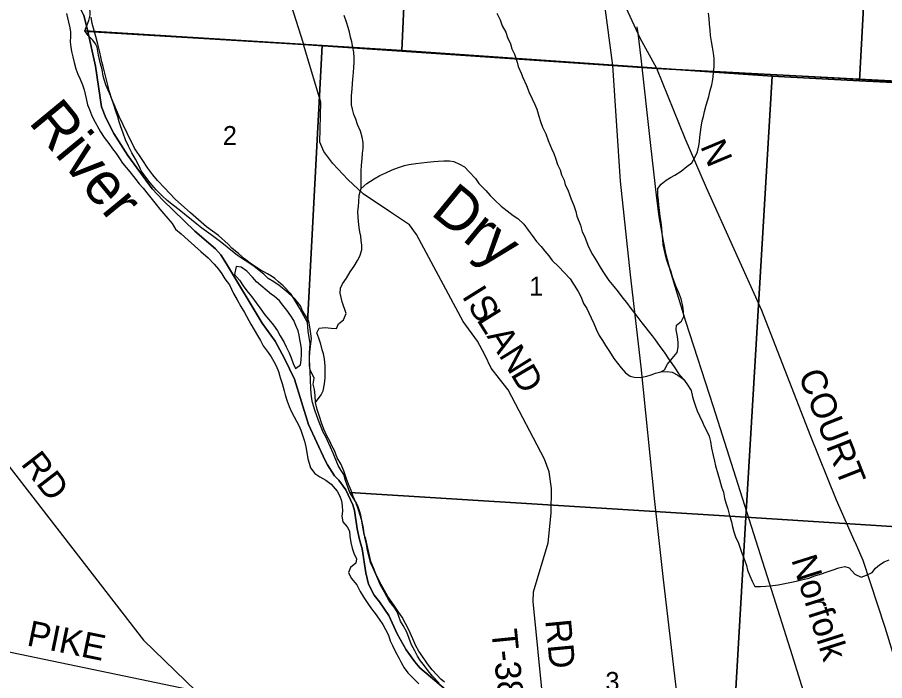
# Model space of a CAD drawing. Extents: x 1643459 to 2064572, y 425441 to 780708.
# Drawn here: x 1832459 to 1842600, y 595739 to 603499 of the extents above; entities that cross this region are included whole.
import ezdxf

# ---------------------------------------------------------------- set-up
doc = ezdxf.new("R2010")
doc.units = 0
for name, color, linetype in [('GM_X_Adjacent_County', 7, 'Continuous'), ('GM_X_City_Street', 7, 'Continuous'), ('GM_X_Interchange_Ramps', 7, 'Continuous'), ('GM_X_Major_River', 7, 'Continuous'), ('GM_X_Major_River_Text', 7, 'Continuous'), ('GM_X_Minor_Lake', 7, 'Continuous'), ('GM_X_Section_Text', 7, 'Continuous'), ('GM_X_State_Route', 7, 'Continuous'), ('GM_X_State_Shield', 7, 'Continuous'), ('GM_X_Township_Road', 7, 'Continuous'), ('GM_X_Township_Road_Text', 7, 'Continuous'), ('GM_X_Unincorporated_Text', 7, 'Continuous'), ('GM_X_US_Route', 7, 'Continuous'), ('RD_X_Wall', 7, 'Continuous')]:
    doc.layers.add(name, color=color, linetype=linetype)

msp = doc.modelspace()

# ---------------------------------------------------------------- linework, layer by layer
at = {"layer": 'GM_X_City_Street'}
for points in [[(1851890, 602317), (1849051, 602434), (1847771, 602487), (1839937, 602900), (1839420, 602936), (1835806, 603183), (1833283, 603334), (1833235, 603525), (1833196, 603598), (1833111, 603919), (1832921, 604454), (1832836, 604727), (1832753, 604952), (1832707, 605041), (1832613, 605226), (1832458, 605407)], [(1833235, 603525), (1833283, 603334), (1833372, 602929), (1833444, 602453), (1833495, 602324), (1833589, 602141), (1833750, 601881), (1834035, 601491), (1834159, 601360), (1834533, 600999), (1834777, 600791), (1834838, 600719), (1834906, 600614), (1835322, 599920), (1835474, 599711), (1835581, 599509), (1835699, 599266), (1835863, 598734), (1836060, 598313), (1836084, 598263), (1836167, 598134), (1836219, 598084), (1836299, 597973), (1836380, 597796), (1836402, 597730), (1836433, 597517), (1836459, 597390), (1836490, 597282), (1836533, 596999), (1836565, 596868), (1836632, 596738), (1836694, 596663), (1836802, 596500), (1836899, 596289), (1837007, 596098), (1837105, 595961), (1837166, 595890), (1837466, 595634)], [(1837466, 595634), (1837166, 595890), (1837105, 595961), (1837007, 596098), (1836899, 596289), (1836802, 596500), (1836694, 596663), (1836632, 596738), (1836565, 596868), (1836533, 596999), (1836490, 597282), (1836459, 597390), (1836433, 597517), (1836402, 597730), (1836380, 597796), (1836299, 597973), (1836219, 598084), (1836167, 598134), (1836084, 598263), (1836060, 598313), (1835863, 598734), (1835699, 599266), (1835581, 599509), (1835474, 599711), (1835322, 599920), (1834906, 600614), (1834838, 600719), (1834777, 600791), (1834533, 600999), (1834159, 601360), (1834035, 601491), (1833750, 601881), (1833589, 602141), (1833495, 602324), (1833444, 602453), (1833372, 602929), (1833283, 603334), (1835806, 603183), (1839420, 602936), (1839937, 602900), (1847771, 602487)]]:
    msp.add_lwpolyline(points, dxfattribs=at)
at = {"layer": 'GM_X_Major_River_Text'}
for points in [[(1835803, 603192), (1835580, 603905), (1835098, 605134), (1834779, 605882), (1834163, 607311), (1836120, 607161), (1836492, 607280), (1836751, 607373), (1837278, 607428), (1837829, 607405)], [(1838603, 595525), (1838490, 596664), (1838495, 596777), (1838665, 597353), (1838702, 597700), (1838703, 597987), (1838679, 598184), (1838624, 598332), (1838198, 599141), (1838095, 599269), (1837999, 599394), (1837926, 599550), (1837840, 599712), (1837673, 599940), (1837127, 600960), (1837043, 601070), (1836824, 601218), (1836501, 601436), (1836322, 601602), (1836147, 601788), (1836041, 601931), (1835994, 602039), (1836008, 602507), (1835806, 603183), (1835803, 603192)], [(1841017, 602840), (1839937, 602900)], [(1845663, 602580), (1841017, 602840)]]:
    msp.add_lwpolyline(points, dxfattribs=at)
at = {"layer": 'GM_X_Minor_Lake'}
for points in [[(1827033, 605132), (1827729, 604232), (1833934, 596214), (1834549, 595618)], [(1839937, 602900), (1839740, 603257), (1839269, 604281), (1839118, 604504), (1839118, 604505)], [(1842256, 597357), (1842035, 597852), (1841727, 598614), (1841163, 600071), (1840518, 601504), (1840268, 602081), (1839937, 602900)], [(1834549, 595618), (1832020, 596144), (1828915, 595974), (1828795, 595972), (1828691, 596005), (1827711, 596647), (1827066, 597064), (1826478, 597464), (1826051, 597755), (1825576, 598057), (1825113, 598342), (1824724, 598588)], [(1843109, 594908), (1842842, 595587), (1842604, 596361), (1842350, 597145), (1842259, 597350), (1842256, 597357)]]:
    msp.add_lwpolyline(points, dxfattribs=at)
at = {"layer": 'GM_X_State_Route'}
for points in [[(1831814, 608761), (1837195, 608395), (1836955, 603110), (1836023, 603169), (1833250, 603342), (1833295, 603462), (1833309, 603524), (1833311, 603566), (1833194, 604051), (1833141, 604253), (1833003, 604686), (1832944, 604860), (1832888, 605022), (1832829, 605138), (1832759, 605243), (1832664, 605343), (1832548, 605466), (1832377, 605625)], [(1837452, 595722), (1837412, 595756), (1837362, 595806), (1837308, 595867), (1837255, 595937), (1837171, 596057), (1837153, 596083), (1837120, 596145), (1837084, 596230), (1837036, 596334), (1836957, 596484), (1836921, 596536), (1836864, 596617), (1836792, 596725), (1836713, 596865), (1836652, 596988), (1836622, 597058), (1836594, 597132), (1836532, 597396), (1836516, 597450), (1836504, 597516), (1836475, 597675), (1836463, 597715), (1836441, 597783), (1836412, 597837), (1836348, 597941), (1840975, 597651), (1840668, 592357)]]:
    msp.add_lwpolyline(points, dxfattribs=at)
for points in [[(1842595, 608085), (1842304, 602757), (1841286, 602812), (1836955, 603110), (1837195, 608395)], [(1842595, 608085), (1842604, 608253), (1846583, 608042), (1846349, 602557), (1842304, 602757)], [(1836023, 603169), (1835850, 599930), (1835808, 600006), (1835763, 600094), (1835715, 600170), (1835661, 600259), (1835566, 600359), (1835512, 600403), (1835468, 600442), (1835430, 600470), (1835383, 600498), (1835299, 600546), (1835183, 600623), (1835115, 600675), (1835048, 600732), (1834966, 600800), (1834924, 600844), (1834813, 600947), (1834671, 601049), (1834482, 601212), (1834306, 601373), (1834179, 601506), (1834098, 601592), (1834042, 601656), (1833983, 601735), (1833919, 601835), (1833828, 601970), (1833742, 602142), (1833651, 602338), (1833556, 602563), (1833547, 602585), (1833495, 602709), (1833464, 602809), (1833450, 602887), (1833432, 602955), (1833409, 603058), (1833391, 603150), (1833372, 603190), (1833342, 603230), (1833286, 603286), (1833250, 603342)], [(1836955, 603110), (1841286, 602812), (1840975, 597651), (1836348, 597941), (1836297, 598080), (1836277, 598150), (1836259, 598174), (1836244, 598196), (1836212, 598258), (1836152, 598400), (1836069, 598583), (1836034, 598645), (1835980, 598781), (1835937, 598905), (1835911, 598993), (1835898, 599061), (1835890, 599149), (1835885, 599268), (1835874, 599502), (1835874, 599576), (1835881, 599682), (1835873, 599752), (1835861, 599826), (1835850, 599930), (1836023, 603169)], [(1841286, 602812), (1842304, 602757), (1846349, 602557), (1846591, 602546), (1846274, 597313), (1840975, 597651)], [(1840975, 597651), (1846274, 597313), (1845968, 591981), (1840668, 592357)]]:
    msp.add_lwpolyline(points, close=True, dxfattribs=at)
at = {"layer": 'GM_X_Township_Road'}
msp.add_lwpolyline([(1841773, 595226), (1841521, 596029), (1841253, 596878), (1840600, 598944), (1840275, 599940), (1840094, 600530), (1840047, 600719), (1840014, 600880), (1839963, 601170), (1839936, 601385), (1839866, 602000), (1839751, 603020), (1839717, 603313), (1839706, 603388)], dxfattribs=at)
at = {"layer": 'GM_X_Unincorporated_Text'}
for points in [[(1833035, 603545), (1833045, 603493), (1833058, 603441), (1833074, 603377), (1833080, 603326), (1833082, 603276), (1833078, 603214), (1833085, 603150), (1833093, 603100), (1833109, 603035), (1833125, 602969), (1833144, 602895), (1833168, 602834), (1833194, 602776), (1833222, 602708), (1833242, 602649), (1833263, 602551), (1833281, 602477), (1833301, 602420), (1833325, 602360), (1833350, 602308), (1833430, 602159), (1833476, 602093), (1833528, 602024), (1833570, 601962), (1833613, 601907), (1833655, 601847), (1833687, 601793), (1833733, 601742), (1833775, 601690), (1833833, 601617), (1833885, 601553), (1833931, 601499), (1833987, 601428), (1834036, 601366), (1834082, 601309), (1834126, 601253), (1834194, 601174), (1834268, 601086), (1834310, 601021), (1834374, 600967), (1834458, 600892), (1834530, 600824), (1834604, 600759), (1834691, 600685), (1834761, 600610), (1834811, 600552), (1834849, 600499), (1834887, 600441), (1834939, 600368), (1834985, 600270), (1835030, 600195), (1835074, 600115), (1835114, 600047), (1835190, 599910), (1835229, 599845), (1835267, 599777), (1835301, 599717), (1835335, 599658), (1835391, 599580), (1835425, 599527), (1835459, 599473), (1835484, 599421), (1835512, 599356), (1835532, 599284), (1835554, 599216), (1835577, 599131), (1835591, 599081), (1835615, 599009), (1835637, 598945), (1835663, 598884), (1835694, 598826), (1835750, 598725), (1835774, 598671), (1835798, 598601)], [(1833961, 601631), (1833905, 601703), (1833882, 601758), (1833840, 601838), (1833798, 601913), (1833760, 601991), (1833725, 602067), (1833695, 602144), (1833667, 602228), (1833651, 602278), (1833633, 602335), (1833614, 602389), (1833582, 602487), (1833564, 602540), (1833534, 602638), (1833521, 602688), (1833497, 602783), (1833473, 602875), (1833461, 602925), (1833448, 602980), (1833436, 603038), (1833422, 603090), (1833400, 603185), (1833377, 603275), (1833335, 603426), (1833322, 603500)], [(1837390, 595710), (1837312, 595791), (1837262, 595853), (1837218, 595913), (1837172, 595972), (1837137, 596026), (1837105, 596090), (1837069, 596159), (1837039, 596231), (1837013, 596308), (1836972, 596384), (1836940, 596434), (1836900, 596543), (1836864, 596599), (1836808, 596674), (1836751, 596776), (1836707, 596857), (1836673, 596931), (1836645, 596992), (1836614, 597062), (1836590, 597122), (1836568, 597201), (1836554, 597263), (1836541, 597335), (1836527, 597399), (1836515, 597462), (1836505, 597524), (1836490, 597596), (1836472, 597663), (1836448, 597737), (1836420, 597817), (1836384, 597892), (1836361, 597962), (1836339, 598020), (1836311, 598087), (1836275, 598193), (1836240, 598276), (1836198, 598346), (1836168, 598432), (1836136, 598487), (1836113, 598541), (1836079, 598603), (1836041, 598680), (1836015, 598754), (1835993, 598831), (1835964, 598913), (1835946, 598995), (1835940, 599074), (1835933, 599144), (1835917, 599206), (1835929, 599276), (1835881, 599375), (1835876, 599427), (1835876, 599511), (1835878, 599582), (1835887, 599654), (1835897, 599740), (1835889, 599798), (1835878, 599877), (1835866, 599943), (1835828, 600009), (1835794, 600066), (1835768, 600124), (1835705, 600205), (1835629, 600273), (1835577, 600317), (1835519, 600362), (1835459, 600404), (1835391, 600445), (1835341, 600495), (1835285, 600537), (1835227, 600584), (1835155, 600636), (1835103, 600667), (1835031, 600715), (1834973, 600760), (1834911, 600810), (1834849, 600860), (1834789, 600909), (1834727, 600953), (1834669, 600994), (1834615, 601032), (1834557, 601078), (1834495, 601129), (1834415, 601195), (1834353, 601246), (1834283, 601296), (1834211, 601355), (1834151, 601409), (1834081, 601482), (1834013, 601564), (1833961, 601631)], [(1835018, 600583), (1835000, 600491), (1835055, 600424), (1835101, 600358), (1835141, 600299), (1835199, 600231), (1835253, 600160), (1835307, 600084), (1835353, 600019), (1835399, 599965), (1835456, 599897), (1835502, 599830), (1835532, 599772), (1835580, 599695), (1835604, 599643), (1835636, 599575), (1835661, 599516), (1835683, 599450), (1835711, 599392), (1835769, 599434), (1835776, 599488), (1835782, 599560), (1835780, 599622), (1835772, 599672), (1835763, 599729), (1835755, 599779), (1835741, 599831), (1835717, 599895), (1835691, 599952), (1835658, 600006), (1835610, 600072), (1835562, 600131), (1835524, 600183), (1835460, 600236), (1835432, 600258)], [(1835432, 600258), (1835256, 600405), (1835208, 600460), (1835142, 600528), (1835078, 600576), (1835018, 600583)], [(1835798, 598601), (1835818, 598542), (1835833, 598474), (1835845, 598410), (1835857, 598336), (1835871, 598283), (1835886, 598229), (1835936, 598163), (1835994, 598124), (1836066, 598084), (1836130, 598039), (1836200, 597957), (1836230, 597898), (1836248, 597844), (1836258, 597784), (1836259, 597722), (1836253, 597664), (1836263, 597597), (1836315, 597539), (1836343, 597487), (1836348, 597430), (1836358, 597354), (1836372, 597288), (1836392, 597229), (1836423, 597165), (1836415, 597113), (1836353, 597065), (1836332, 597005), (1836362, 596939), (1836430, 596860), (1836468, 596784), (1836512, 596711), (1836563, 596631), (1836599, 596578), (1836643, 596524), (1836691, 596458), (1836733, 596397), (1836765, 596337), (1836799, 596270), (1836820, 596204), (1836846, 596150), (1836886, 596069), (1836918, 596007), (1836948, 595951), (1836981, 595888), (1837023, 595832), (1837101, 595753), (1837155, 595701)]]:
    msp.add_lwpolyline(points, dxfattribs=at)
at = {"layer": 'GM_X_US_Route'}
for points in [[(1836479, 601496), (1836478, 601704), (1836482, 601764), (1836490, 601847), (1836495, 601907), (1836503, 601967), (1836501, 602035), (1836492, 602096), (1836472, 602166), (1836438, 602244), (1836416, 602307), (1836394, 602363), (1836377, 602425), (1836367, 602477), (1836365, 602528), (1836365, 602584), (1836372, 602658), (1836376, 602726), (1836382, 602776), (1836391, 602855), (1836395, 602917), (1836399, 602967), (1836399, 603027), (1836392, 603091), (1836382, 603146), (1836370, 603214), (1836356, 603266), (1836341, 603326), (1836327, 603381), (1836307, 603443), (1836279, 603521)], [(1838065, 603546), (1838105, 603469), (1838127, 603401), (1838171, 603325), (1838190, 603264), (1838226, 603190), (1838242, 603130), (1838270, 603069), (1838303, 602975), (1838315, 602923), (1838351, 602844), (1838369, 602794), (1838411, 602703), (1838444, 602619), (1838480, 602545), (1838508, 602480), (1838532, 602424)], [(1839981, 599351), (1840027, 599377), (1840061, 599443), (1840114, 599509), (1840172, 599577), (1840187, 599641), (1840185, 599696), (1840177, 599766), (1840164, 599842), (1840166, 599896), (1840226, 599946), (1840250, 599998), (1840249, 600052), (1840239, 600121), (1840219, 600205), (1840192, 600277), (1840164, 600346), (1840140, 600410), (1840118, 600464), (1840098, 600533), (1840071, 600601), (1840051, 600669), (1840035, 600738), (1840011, 600838), (1840006, 600904), (1840000, 600975), (1839996, 601031), (1839987, 601103), (1839977, 601169), (1839967, 601242), (1839959, 601302), (1839954, 601360), (1839948, 601416), (1839948, 601495), (1839987, 601547), (1840045, 601593), (1840095, 601624), (1840148, 601652), (1840220, 601698), (1840288, 601752), (1840345, 601798), (1840385, 601868), (1840412, 601926), (1840428, 601994), (1840436, 602046), (1840439, 602099), (1840445, 602155), (1840453, 602215), (1840467, 602287), (1840480, 602339), (1840492, 602399), (1840512, 602470), (1840529, 602522), (1840543, 602574), (1840561, 602642), (1840578, 602708), (1840590, 602772), (1840600, 602844), (1840605, 602927), (1840605, 603017), (1840597, 603079), (1840588, 603150), (1840576, 603218), (1840562, 603288), (1840559, 603348), (1840551, 603419), (1840547, 603487), (1840539, 603549)], [(1838532, 602424), (1838557, 602342), (1838577, 602281), (1838599, 602213), (1838637, 602137), (1838667, 602060), (1838706, 601964), (1838730, 601905), (1838752, 601853), (1838774, 601777), (1838807, 601714), (1838823, 601658), (1838851, 601596), (1838865, 601539), (1838895, 601481), (1838934, 601373), (1838964, 601298), (1838990, 601226), (1839002, 601174), (1839043, 601069), (1839063, 600989), (1839091, 600938), (1839131, 600834), (1839156, 600776), (1839182, 600725), (1839222, 600663), (1839272, 600578), (1839304, 600526), (1839374, 600419), (1839433, 600349), (1839483, 600287), (1839539, 600214), (1839583, 600162), (1839633, 600093), (1839675, 600039), (1839713, 599989), (1839761, 599926), (1839880, 599775), (1839916, 599725), (1839962, 599660), (1840028, 599572), (1840074, 599505), (1840110, 599449), (1840145, 599399), (1840189, 599334), (1840247, 599266)], [(1836454, 601419), (1836479, 601496), (1836547, 601554), (1836632, 601609), (1836696, 601647), (1836767, 601681), (1836841, 601715), (1836915, 601743), (1836986, 601764), (1837036, 601778), (1837120, 601790), (1837185, 601796), (1837251, 601803), (1837329, 601813), (1837381, 601817), (1837447, 601821), (1837512, 601820), (1837562, 601812), (1837630, 601782), (1837688, 601751), (1837742, 601693), (1837816, 601614), (1837854, 601554), (1837938, 601473), (1837989, 601413), (1838043, 601360), (1838117, 601288), (1838187, 601237), (1838257, 601179), (1838311, 601145), (1838381, 601080), (1838433, 601008), (1838479, 600947), (1838529, 600875), (1838583, 600818), (1838627, 600762), (1838675, 600707), (1838714, 600655), (1838792, 600579), (1838854, 600514), (1838924, 600439), (1838968, 600365), (1839018, 600293), (1839052, 600224), (1839079, 600150), (1839119, 600093), (1839143, 600043), (1839167, 599983), (1839201, 599917), (1839226, 599852), (1839262, 599778), (1839300, 599717), (1839336, 599661), (1839384, 599589), (1839434, 599508), (1839521, 599397), (1839571, 599341), (1839623, 599303), (1839673, 599288), (1839742, 599286), (1839820, 599300), (1839870, 599316), (1839920, 599337), (1839981, 599351), (1840055, 599355), (1840117, 599349), (1840183, 599312), (1840247, 599266), (1840285, 599213), (1840339, 599133), (1840355, 599061), (1840368, 599010), (1840388, 598950), (1840406, 598894), (1840436, 598838), (1840470, 598765), (1840488, 598715), (1840519, 598659), (1840547, 598598), (1840563, 598536), (1840577, 598458), (1840594, 598373), (1840610, 598305), (1840624, 598253), (1840650, 598160), (1840669, 598092), (1840693, 598006), (1840715, 597943), (1840729, 597873), (1840744, 597819), (1840766, 597748), (1840784, 597670), (1840810, 597598), (1840821, 597539), (1840837, 597481), (1840857, 597421), (1840891, 597346), (1840922, 597254), (1840964, 597141), (1840986, 597087), (1840998, 597033)], [(1835946, 598995), (1836013, 599081), (1836033, 599131), (1836051, 599210), (1836058, 599282), (1836060, 599334), (1836058, 599420), (1836049, 599503), (1836037, 599561), (1836025, 599611), (1836007, 599675), (1835985, 599746), (1835960, 599810), (1835990, 599862), (1836058, 599872), (1836128, 599862), (1836189, 599857), (1836215, 599913), (1836271, 599961), (1836302, 600033), (1836258, 600170), (1836244, 600222), (1836235, 600272), (1836239, 600329), (1836261, 600383), (1836308, 600449), (1836350, 600521), (1836397, 600589), (1836435, 600653), (1836463, 600705), (1836486, 600779), (1836486, 600833), (1836480, 600890), (1836474, 600940), (1836465, 600990), (1836455, 601042), (1836447, 601110), (1836443, 601163), (1836442, 601229), (1836448, 601287), (1836452, 601339), (1836454, 601419)], [(1840998, 597033), (1841023, 596967), (1841049, 596904), (1841083, 596840), (1841149, 596840), (1841212, 596845), (1841294, 596853), (1841354, 596861), (1841432, 596877), (1841511, 596890), (1841565, 596902), (1841627, 596918), (1841712, 596940), (1841784, 596967), (1841848, 596985), (1841929, 597013), (1841987, 597033), (1842065, 597060), (1842134, 597076), (1842184, 597060), (1842252, 596987), (1842324, 596949), (1842386, 596973), (1842452, 597003), (1842491, 597057), (1842541, 597094), (1842595, 597128), (1842654, 597154)]]:
    msp.add_lwpolyline(points, dxfattribs=at)
at = {"layer": 'RD_X_Wall'}
msp.add_lwpolyline([(1841570, 590051), (1841464, 590384), (1840952, 591925), (1840750, 592618), (1840551, 593207), (1840454, 593588), (1840392, 593881), (1840336, 594171), (1840299, 594426), (1840171, 595596), (1840015, 596921), (1839914, 597835), (1839752, 599409), (1839627, 600488), (1839512, 601581), (1839420, 602936), (1839323, 603672), (1839178, 604294), (1839060, 604590), (1839024, 604692), (1838981, 604799), (1838688, 605446), (1838632, 605574)], dxfattribs=at)

# ---------------------------------------------------------------- texts
at = {"layer": 'GM_X_Adjacent_County'}
for s, p in [('2', (1834862, 602006)), ('1', (1838444, 600244)), ('3', (1839335, 595620))]:
    msp.add_text(s, height=221, rotation=0, dxfattribs=at).set_placement(p)
at = {"layer": 'GM_X_Interchange_Ramps'}
msp.add_text('Dry', height=500, rotation=320.693, dxfattribs=at).set_placement((1837278, 601202))
at = {"layer": 'GM_X_Major_River'}
for s, rotation, p in [('I', 302.0294, (1837650, 600237)), ('S', 302.0281, (1837716, 600132)), ('L', 302.0258, (1837823, 599961)), ('A', 302.0289, (1837942, 599770)), ('N', 301.9228, (1838082, 599547)), ('D', 300.4159, (1838221, 599324)), ('RD', 275.4159, (1838632, 596445)), ('T-38', 275.675, (1838001, 596329))]:
    msp.add_text(s, height=300, rotation=rotation, dxfattribs=at).set_placement(p)
at = {"layer": 'GM_X_Section_Text'}
for s, rotation, p in [('N', 292.6926, (1840440, 601992)), ('COURT', 291.4273, (1841586, 599317)), ('RD', 307.6602, (1832492, 598274)), ('PIKE', 348.4471, (1832558, 596153))]:
    msp.add_text(s, height=300, rotation=rotation, dxfattribs=at).set_placement(p)
at = {"layer": 'GM_X_State_Shield'}
msp.add_text('River', height=500, rotation=309.5196, dxfattribs=at).set_placement((1832581, 602270))
at = {"layer": 'GM_X_Township_Road_Text'}
msp.add_text('Norfolk', height=299, rotation=287.5586, dxfattribs=at).set_placement((1841506, 597156))

doc.saveas('drawing.dxf')
